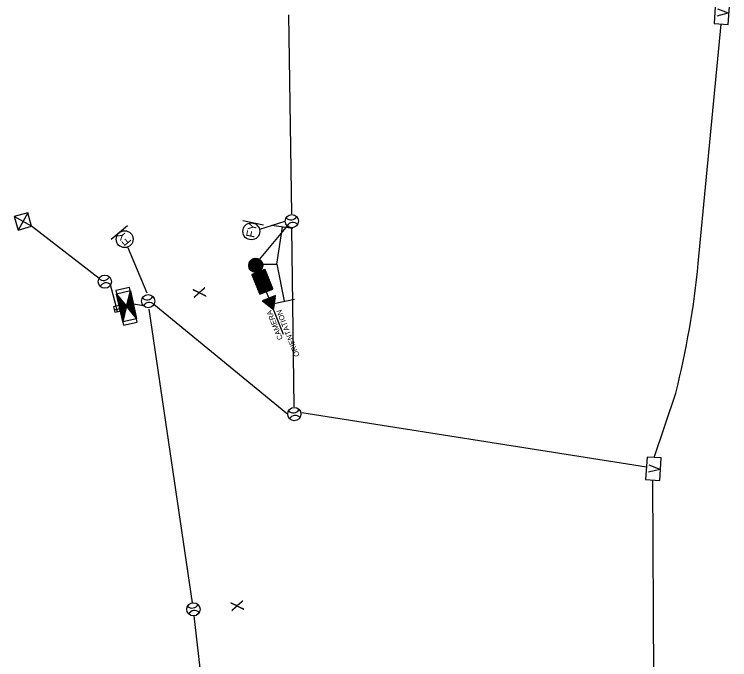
# Model space of a CAD drawing. Extents: x 601562 to 605316, y 332050 to 402250.
# Drawn here: x 601780.7 to 602185.9, y 355227.3 to 355592.7 of the extents above; entities that cross this region are included whole.
import ezdxf

# ---------------------------------------------------------------- set-up
doc = ezdxf.new("R2010")
doc.units = 0
for name, color, linetype in [('Default', 7, 'Continuous'), ('P_FTMS', 7, 'Continuous'), ('P_FTMSConduit', 7, 'Continuous'), ('P_MISC_TXT_1A', 7, 'Continuous')]:
    doc.layers.add(name, color=color, linetype=linetype)

# ---------------------------------------------------------------- blocks, each defined once
blk = doc.blocks.new('FMB_1')
at = {"layer": 'P_FTMS'}
for p, q in [((24.4, -24.4), (-24.4, 24.4)), ((-24.4, -24.4), (24.4, 24.4))]:
    blk.add_line(p, q, dxfattribs=at)
blk.add_lwpolyline([(24.4, -24.4), (24.4, 24.4), (-24.4, 24.4), (-24.4, -24.4)], close=True, dxfattribs=at)
blk = doc.blocks.new('POINT_DISPLAY')
at = {"layer": 'Default'}
blk.add_line((0, 0), (0, 0), dxfattribs=at)
blk = doc.blocks.new('FCS')
at = {"layer": 'P_FTMS'}
for p, q in [((-92.7, 0), (0, 0)), ((1.3, -0.8), (4.9, 2.8)), ((4.9, -2.8), (1.3, 0.8)), ((2.6, -1.5), (9.8, 5.7)), ((9.8, -5.7), (2.6, 1.5)), ((3.9, -2.3), (14.7, 8.5)), ((14.7, -8.5), (3.9, 2.3)), ((5.2, -3), (19.6, 11.3)), ((19.6, -11.3), (5.2, 3)), ((6.6, -3.8), (24.5, 14.1)), ((24.5, -14.2), (6.6, 3.8)), ((7.9, -4.5), (29.4, 17)), ((29.4, -17), (7.9, 4.5)), ((9.2, -5.3), (34.3, 19.8)), ((34.3, -19.8), (9.2, 5.3)), ((10.5, -6.1), (39.2, 22.6)), ((39.2, -22.6), (10.5, 6.1)), ((11.8, -6.8), (42, 23.4)), ((42, -23.4), (11.8, 6.8)), ((13.1, -7.6), (42, 21.3)), ((42, -21.3), (13.1, 7.6)), ((14.4, -8.3), (42, 19.3)), ((42, -19.3), (14.4, 8.3)), ((15.7, -9.1), (42, 17.2)), ((42, -17.2), (15.7, 9.1)), ((17, -9.8), (42, 15.1)), ((42, -15.1), (17.1, 9.8)), ((18.4, -10.6), (42, 13.1)), ((42, -13.1), (18.4, 10.6)), ((42, -11), (19.7, 11.4)), ((19.7, -11.4), (42, 11)), ((42, -8.9), (21, 12.1)), ((21, -12.1), (42, 8.9)), ((42, -6.8), (22.3, 12.9)), ((22.3, -12.9), (42, 6.8)), ((42, -4.8), (23.6, 13.6)), ((23.6, -13.6), (42, 4.8)), ((42, -2.7), (24.9, 14.4)), ((24.9, -14.4), (42, 2.7)), ((42, -0.6), (26.2, 15.1)), ((26.2, -15.2), (42, 0.6)), ((42, 1.4), (27.5, 15.9)), ((42, 3.5), (28.9, 16.7)), ((42, 5.6), (30.2, 17.4)), ((42, 7.6), (31.5, 18.2)), ((42, 9.7), (32.8, 18.9)), ((42, 11.8), (34.1, 19.7)), ((42, 13.8), (35.4, 20.4)), ((42, 15.9), (36.7, 21.2)), ((42, 18), (38, 22)), ((42, 20.1), (39.3, 22.7)), ((42, 22.1), (40.7, 23.5)), ((42, 24.2), (42, 24.2)), ((66.4, 0.1), (42, 0.1)), ((66.4, -24.3), (115.2, 24.5)), ((66.4, -13.9), (104.8, 24.5)), ((66.4, -3.6), (94.5, 24.5)), ((66.4, 6.8), (84.1, 24.5)), ((66.4, 17.1), (73.8, 24.5)), ((66.4, -22.2), (113.1, 24.5)), ((66.4, -11.9), (102.8, 24.5)), ((66.4, -1.5), (92.4, 24.5)), ((66.4, 8.8), (82.1, 24.5)), ((66.4, 19.2), (71.7, 24.5)), ((66.4, -20.1), (111, 24.5)), ((66.4, -9.8), (100.7, 24.5)), ((66.4, 0.6), (90.3, 24.5)), ((66.4, 10.9), (80, 24.5)), ((66.4, 21.2), (69.6, 24.5)), ((66.4, -18.1), (109, 24.5)), ((66.4, -7.7), (98.6, 24.5)), ((66.4, 2.6), (88.3, 24.5)), ((66.4, 13), (77.9, 24.5)), ((66.4, 23.3), (67.6, 24.5)), ((66.4, -16), (106.9, 24.5)), ((66.4, -5.7), (96.5, 24.5)), ((66.4, 4.7), (86.2, 24.5)), ((66.4, 15), (75.9, 24.5)), ((114, -24.3), (66.4, 23.3)), ((111.9, -24.3), (66.4, 21.2)), ((109.9, -24.3), (66.4, 19.2)), ((107.8, -24.3), (66.4, 17.1)), ((105.7, -24.3), (66.4, 15)), ((103.6, -24.3), (66.4, 13)), ((101.6, -24.3), (66.4, 10.9)), ((99.5, -24.3), (66.4, 8.8)), ((97.4, -24.3), (66.4, 6.8)), ((95.4, -24.3), (66.4, 4.7)), ((93.3, -24.3), (66.4, 2.6)), ((91.2, -24.3), (66.4, 0.6)), ((116.1, -24.3), (67.3, 24.5)), ((68.5, -24.3), (117.2, 24.5)), ((118.1, -24.3), (69.4, 24.5)), ((70.5, -24.3), (119.3, 24.5)), ((120.2, -24.3), (71.4, 24.5)), ((72.6, -24.3), (121.4, 24.5)), ((122.3, -24.3), (73.5, 24.5)), ((74.7, -24.3), (123.4, 24.5)), ((124.3, -24.3), (75.6, 24.5)), ((76.7, -24.3), (125.5, 24.5)), ((126.4, -24.3), (77.6, 24.5)), ((78.8, -24.3), (127.6, 24.5)), ((128.5, -24.3), (79.7, 24.5)), ((80.9, -24.3), (129.7, 24.5)), ((130.5, -24.3), (81.8, 24.5)), ((83, -24.3), (131.7, 24.5)), ((132.6, -24.3), (83.8, 24.5)), ((85, -24.3), (133.8, 24.5)), ((134.7, -24.3), (85.9, 24.5)), ((87.1, -24.3), (135.9, 24.5)), ((136.7, -24.3), (88, 24.5)), ((89.2, -24.3), (137.9, 24.5)), ((138.8, -24.3), (90.1, 24.5)), ((91.2, -24.3), (139.6, 24.1)), ((139.6, -22.9), (92.1, 24.5)), ((93.3, -24.3), (139.6, 22)), ((139.6, -20.9), (94.2, 24.5)), ((95.4, -24.3), (139.6, 19.9)), ((139.6, -18.8), (96.3, 24.5)), ((97.4, -24.3), (139.6, 17.8)), ((139.6, -16.7), (98.3, 24.5)), ((99.5, -24.3), (139.6, 15.8)), ((139.6, -14.7), (100.4, 24.5)), ((101.6, -24.3), (139.6, 13.7)), ((139.6, -12.6), (102.5, 24.5)), ((103.6, -24.3), (139.6, 11.6)), ((139.6, -10.5), (104.5, 24.5)), ((105.7, -24.3), (139.6, 9.6)), ((139.6, -8.5), (106.6, 24.5)), ((107.8, -24.3), (139.6, 7.5)), ((139.6, -6.4), (108.7, 24.5)), ((109.9, -24.3), (139.6, 5.4)), ((110.4, 0.1), (112, 0.1)), ((139.6, -4.3), (110.7, 24.5)), ((111.9, -24.3), (139.6, 3.4)), ((139.6, -2.3), (112.8, 24.5)), ((114, -24.3), (139.6, 1.3)), ((139.6, -0.2), (114.9, 24.5)), ((139.6, 1.9), (116.9, 24.5)), ((139.6, 4), (119, 24.5)), ((139.6, 6), (121.1, 24.5)), ((139.6, 8.1), (123.2, 24.5)), ((139.6, 10.2), (125.2, 24.5)), ((139.6, 12.2), (127.3, 24.5)), ((139.6, 14.3), (129.4, 24.5)), ((139.6, 16.4), (131.4, 24.5)), ((139.6, 18.4), (133.5, 24.5)), ((139.6, 20.5), (135.6, 24.5)), ((139.6, 22.6), (137.6, 24.5)), ((139.6, 0.6), (163.5, 24.4)), ((165.5, -24.2), (139.6, 1.6)), ((139.7, -1.4), (165.4, 24.4)), ((139.8, 2.9), (161.2, 24.3)), ((139.8, -3.3), (167.3, 24.2)), ((167.3, -24), (139.9, 3.5)), ((140.1, 5.2), (158.7, 23.9)), ((169.1, -23.7), (140.1, 5.3)), ((140.2, -5), (169.1, 23.9)), ((140.6, -6.7), (170.7, 23.4)), ((170.8, -23.3), (140.6, 6.9)), ((141, 8.2), (155.9, 23.1)), ((141.1, -8.2), (172.3, 23)), ((172.3, -22.7), (141.1, 8.5)), ((141.7, -9.7), (173.8, 22.3)), ((173.8, -22.2), (141.7, 9.9)), ((142.3, -11.1), (175.2, 21.7)), ((175.2, -21.5), (142.4, 11.3)), ((142.7, 12), (152.2, 21.5)), ((143.1, -12.4), (176.5, 20.9)), ((176.5, -20.7), (143.1, 12.7)), ((143.9, -13.7), (177.7, 20.1)), ((177.8, -19.9), (143.9, 13.9)), ((144.8, -14.9), (179, 19.3)), ((178.9, -19), (144.8, 15.1)), ((180.1, -18.1), (145.7, 16.3)), ((145.8, -16), (180.1, 18.3)), ((146.7, -17.1), (181.1, 17.3)), ((181.2, -17.1), (146.8, 17.3)), ((182.1, -16), (147.8, 18.3)), ((147.8, -18.1), (182.2, 16.3)), ((183.1, -14.9), (148.9, 19.3)), ((149, -19), (183.1, 15.1)), ((184, -13.7), (150.1, 20.1)), ((150.1, -19.9), (184, 13.9)), ((184.8, -12.4), (151.4, 20.9)), ((151.4, -20.7), (184.8, 12.7)), ((185.5, -11.2), (152.7, 21.7)), ((152.7, -21.5), (185.5, 11.3)), ((186.2, -9.7), (154.1, 22.3)), ((154.1, -22.2), (186.2, 9.9)), ((186.8, -8.2), (155.6, 23)), ((155.6, -22.7), (186.8, 8.5)), ((157.1, -23.3), (187.3, 6.9)), ((187.3, -6.7), (157.2, 23.4)), ((187.7, -5), (158.8, 23.9)), ((158.8, -23.7), (187.8, 5.3)), ((188.1, -3.3), (160.5, 24.2)), ((160.6, -24), (188, 3.5)), ((188.2, -1.4), (162.4, 24.4)), ((162.4, -24.2), (188.2, 1.6)), ((188.3, 0.6), (164.4, 24.5)), ((188.1, 2.9), (166.7, 24.3)), ((187.8, 5.2), (169.2, 23.9)), ((186.9, 8.2), (172, 23.1)), ((185.2, 12), (175.7, 21.4)), ((27.5, -15.9), (42, -1.4)), ((28.9, -16.7), (42, -3.5)), ((30.2, -17.4), (42, -5.6)), ((31.5, -18.2), (42, -7.6)), ((32.8, -18.9), (42, -9.7)), ((34.1, -19.7), (42, -11.8)), ((35.4, -20.5), (42, -13.8)), ((36.7, -21.2), (42, -15.9)), ((38, -22), (42, -18)), ((39.3, -22.7), (42, -20.1)), ((40.7, -23.5), (42, -22.1)), ((42, -24.2), (42, -24.2)), ((89.2, -24.3), (66.4, -1.5)), ((87.1, -24.3), (66.4, -3.6)), ((85, -24.3), (66.4, -5.7)), ((83, -24.3), (66.4, -7.7)), ((80.9, -24.3), (66.4, -9.8)), ((78.8, -24.3), (66.4, -11.9)), ((76.7, -24.3), (66.4, -13.9)), ((74.7, -24.3), (66.4, -16)), ((72.6, -24.3), (66.4, -18.1)), ((70.5, -24.3), (66.4, -20.1)), ((68.5, -24.3), (66.4, -22.2)), ((116.1, -24.3), (139.6, -0.8)), ((118.1, -24.3), (139.6, -2.8)), ((120.2, -24.3), (139.6, -4.9)), ((122.3, -24.3), (139.6, -7)), ((124.3, -24.3), (139.6, -9.1)), ((126.4, -24.3), (139.6, -11.1)), ((128.5, -24.3), (139.6, -13.2)), ((130.5, -24.3), (139.6, -15.3)), ((132.6, -24.3), (139.6, -17.3)), ((134.7, -24.3), (139.6, -19.4)), ((136.7, -24.3), (139.6, -21.5)), ((138.8, -24.3), (139.6, -23.5)), ((163.4, -24.2), (139.6, -0.4)), ((161.2, -24.1), (139.7, -2.6)), ((158.7, -23.6), (140.2, -5.1)), ((155.8, -22.8), (141, -8)), ((152, -21), (142.7, -11.8)), ((164.5, -24.2), (188.2, -0.4)), ((166.7, -24.1), (188.1, -2.6)), ((169.2, -23.7), (187.7, -5.1)), ((172.1, -22.8), (186.9, -8)), ((175.9, -21), (185.2, -11.8))]:
    blk.add_line(p, q, dxfattribs=at)
for points in [[(42, -24.3), (42, 24.3), (0, 0)], [(139.6, 24.5), (66.4, 24.5), (66.4, -24.3), (139.6, -24.3)]]:
    blk.add_lwpolyline(points, close=True, dxfattribs=at)
blk.add_circle((163.9, 0.1), 24.4, dxfattribs=at)
for p in [(0, 0), (110.4, 0.1)]:
    blk.add_blockref('POINT_DISPLAY', p, dxfattribs=at)
at = {"layer": 'P_MISC_TXT_1A'}
for s, height, p in [('CAMERA', 18.29, (-105.8, 7)), ('ORIENTATION', 18.288, (-181.1, -25))]:
    blk.add_text(s, height=height, rotation=360, dxfattribs=at).set_placement(p)
blk = doc.blocks.new('FTMS_FCV')
at = {"layer": 'P_FTMS'}
blk.add_line((12.7, 16.3), (0.6, -21.9), dxfattribs=at)
blk.add_lwpolyline([(39.1, 24.4), (-39.1, 24.4), (-39.1, -24.4), (39.1, -24.4)], close=True, dxfattribs=at)
blk.add_lwpolyline([(-12.1, 16.2), (0.6, -21.9)], dxfattribs=at)
blk = doc.blocks.new('FTMS_FCB')
at = {"layer": 'P_FTMS'}
for p, q in [((-48.3, 24.1), (-48, 24.4)), ((-45.5, 22.7), (-47.1, 24.4)), ((-46.9, 23.4), (-46, 24.4)), ((-45.5, 22.8), (-43.9, 24.4)), ((-41.4, 20.7), (-45.1, 24.4)), ((-44.1, 22.1), (-41.8, 24.4)), ((-37.2, 18.6), (-43, 24.4)), ((-42.8, 21.4), (-39.8, 24.4)), ((-41.4, 20.7), (-37.7, 24.4)), ((-33.1, 16.5), (-40.9, 24.4)), ((-40, 20), (-35.6, 24.4)), ((-29, 14.5), (-38.9, 24.4)), ((-38.6, 19.3), (-33.6, 24.4)), ((-37.2, 18.6), (-31.5, 24.4)), ((-24.8, 12.4), (-36.8, 24.4)), ((-35.9, 17.9), (-29.4, 24.4)), ((-20.7, 10.3), (-34.7, 24.4)), ((-34.5, 17.2), (-27.3, 24.4)), ((-33.1, 16.5), (-25.3, 24.4)), ((-16.5, 8.3), (-32.7, 24.4)), ((-31.7, 15.9), (-23.2, 24.4)), ((-12.4, 6.2), (-30.6, 24.4)), ((-30.3, 15.2), (-21.1, 24.4)), ((-29, 14.5), (-19.1, 24.4)), ((-8.3, 4.1), (-28.5, 24.4)), ((-27.6, 13.8), (-17, 24.4)), ((-4.1, 2.1), (-26.4, 24.4)), ((-26.2, 13.1), (-14.9, 24.4)), ((-24.8, 12.4), (-12.9, 24.4)), ((0, 0), (-24.4, 24.4)), ((-24.4, -24.4), (0, 0)), ((-23.5, 11.7), (-10.8, 24.4)), ((1.4, 0.7), (-22.3, 24.4)), ((-22.1, 11), (-8.7, 24.4)), ((-20.7, 10.3), (-6.7, 24.4)), ((2.8, 1.4), (-20.2, 24.4)), ((-19.3, 9.7), (-4.6, 24.4)), ((4.1, 2.1), (-18.2, 24.4)), ((-17.9, 9), (-2.5, 24.4)), ((-16.6, 8.3), (-0.4, 24.4)), ((5.5, 2.8), (-16.1, 24.4)), ((-15.2, 7.6), (1.6, 24.4)), ((6.9, 3.4), (-14, 24.4)), ((-13.8, 6.9), (3.7, 24.4)), ((-12.4, 6.2), (5.8, 24.4)), ((8.3, 4.1), (-12, 24.4)), ((-11, 5.5), (7.8, 24.4)), ((9.7, 4.8), (-9.9, 24.4)), ((-9.7, 4.8), (9.9, 24.4)), ((-8.3, 4.1), (12, 24.4)), ((11, 5.5), (-7.8, 24.4)), ((-6.9, 3.4), (14, 24.4)), ((12.4, 6.2), (-5.8, 24.4)), ((-5.5, 2.8), (16.1, 24.4)), ((-4.1, 2.1), (18.2, 24.4)), ((13.8, 6.9), (-3.7, 24.4)), ((-2.8, 1.4), (20.2, 24.4)), ((15.2, 7.6), (-1.6, 24.4)), ((-1.4, 0.7), (22.3, 24.4)), ((0, 0), (24.4, 24.4)), ((24.4, -24.4), (0, 0)), ((16.6, 8.3), (0.4, 24.4)), ((17.9, 9), (2.5, 24.4)), ((4.1, 2.1), (26.5, 24.4)), ((19.3, 9.7), (4.6, 24.4)), ((20.7, 10.3), (6.7, 24.4)), ((8.3, 4.1), (28.5, 24.4)), ((22.1, 11), (8.7, 24.4)), ((23.4, 11.7), (10.8, 24.4)), ((12.4, 6.2), (30.6, 24.4)), ((24.8, 12.4), (12.9, 24.4)), ((26.2, 13.1), (14.9, 24.4)), ((16.6, 8.3), (32.7, 24.4)), ((27.6, 13.8), (17, 24.4)), ((29, 14.5), (19.1, 24.4)), ((20.7, 10.3), (34.7, 24.4)), ((30.3, 15.2), (21.1, 24.4)), ((31.7, 15.9), (23.2, 24.4)), ((24.8, 12.4), (36.8, 24.4)), ((33.1, 16.6), (25.3, 24.4)), ((34.5, 17.2), (27.3, 24.4)), ((29, 14.5), (38.9, 24.4)), ((35.9, 17.9), (29.4, 24.4)), ((37.2, 18.6), (31.5, 24.4)), ((33.1, 16.6), (40.9, 24.4)), ((38.6, 19.3), (33.5, 24.4)), ((40, 20), (35.6, 24.4)), ((37.2, 18.6), (43, 24.4)), ((41.4, 20.7), (37.7, 24.4)), ((42.8, 21.4), (39.8, 24.4)), ((41.4, 20.7), (45.1, 24.4)), ((44.1, 22.1), (41.8, 24.4)), ((45.5, 22.8), (43.9, 24.4)), ((45.5, 22.8), (47.1, 24.4)), ((46.9, 23.5), (46, 24.4)), ((48.3, 24.1), (48, 24.4)), ((-48, -24.4), (-48.3, -24.1)), ((-47.2, -24.4), (-45.5, -22.8)), ((-45.9, -24.4), (-46.9, -23.5)), ((-43.9, -24.4), (-45.5, -22.8)), ((-45.1, -24.4), (-41.4, -20.7)), ((-41.8, -24.4), (-44.1, -22.1)), ((-43, -24.4), (-37.3, -18.6)), ((-39.7, -24.4), (-42.8, -21.4)), ((-37.7, -24.4), (-41.4, -20.7)), ((-41, -24.4), (-33.1, -16.6)), ((-35.6, -24.4), (-40, -20)), ((-38.9, -24.4), (-29, -14.5)), ((-33.5, -24.4), (-38.6, -19.3)), ((-31.5, -24.4), (-37.2, -18.6)), ((-36.8, -24.4), (-24.8, -12.4)), ((-29.4, -24.4), (-35.9, -17.9)), ((-34.8, -24.4), (-20.7, -10.4)), ((-27.3, -24.4), (-34.5, -17.2)), ((-25.3, -24.4), (-33.1, -16.6)), ((-32.7, -24.4), (-16.6, -8.3)), ((-23.2, -24.4), (-31.7, -15.9)), ((-30.6, -24.4), (-12.4, -6.2)), ((-21.1, -24.4), (-30.3, -15.2)), ((-19, -24.4), (-29, -14.5)), ((-28.5, -24.4), (-8.3, -4.1)), ((-17, -24.4), (-27.6, -13.8)), ((-26.5, -24.4), (-4.1, -2.1)), ((-14.9, -24.4), (-26.2, -13.1)), ((-12.8, -24.4), (-24.8, -12.4)), ((-10.8, -24.4), (-23.4, -11.7)), ((-22.3, -24.4), (1.4, -0.7)), ((-8.7, -24.4), (-22.1, -11)), ((-6.6, -24.4), (-20.7, -10.3)), ((-20.3, -24.4), (2.8, -1.4)), ((-4.6, -24.4), (-19.3, -9.7)), ((-18.2, -24.4), (4.1, -2.1)), ((-2.5, -24.4), (-17.9, -9)), ((-0.4, -24.4), (-16.6, -8.3)), ((-16.1, -24.4), (5.5, -2.8)), ((1.6, -24.4), (-15.2, -7.6)), ((-14.1, -24.4), (6.9, -3.4)), ((3.7, -24.4), (-13.8, -6.9)), ((5.8, -24.4), (-12.4, -6.2)), ((-12, -24.4), (8.3, -4.1)), ((7.8, -24.4), (-11, -5.5)), ((-9.9, -24.4), (9.7, -4.8)), ((9.9, -24.4), (-9.7, -4.8)), ((12, -24.4), (-8.3, -4.1)), ((-7.8, -24.4), (11, -5.5)), ((14.1, -24.4), (-6.9, -3.5)), ((-5.8, -24.4), (12.4, -6.2)), ((16.1, -24.4), (-5.5, -2.8)), ((18.2, -24.4), (-4.1, -2.1)), ((-3.7, -24.4), (13.8, -6.9)), ((20.3, -24.4), (-2.8, -1.4)), ((-1.6, -24.4), (15.2, -7.6)), ((22.3, -24.4), (-1.4, -0.7)), ((0.4, -24.4), (16.6, -8.3)), ((2.5, -24.4), (17.9, -9)), ((26.5, -24.4), (4.1, -2.1)), ((4.6, -24.4), (19.3, -9.7)), ((6.6, -24.4), (20.7, -10.3)), ((28.5, -24.4), (8.3, -4.1)), ((8.7, -24.4), (22.1, -11)), ((10.8, -24.4), (23.4, -11.7)), ((30.6, -24.4), (12.4, -6.2)), ((12.8, -24.4), (24.8, -12.4)), ((14.9, -24.4), (26.2, -13.1)), ((32.7, -24.4), (16.6, -8.3)), ((17, -24.4), (27.6, -13.8)), ((19.1, -24.4), (29, -14.5)), ((34.7, -24.4), (20.7, -10.3)), ((21.1, -24.4), (30.3, -15.2)), ((23.2, -24.4), (31.7, -15.9)), ((36.8, -24.4), (24.8, -12.4)), ((25.3, -24.4), (33.1, -16.6)), ((27.3, -24.4), (34.5, -17.2)), ((38.9, -24.4), (29, -14.5)), ((29.4, -24.4), (35.9, -17.9)), ((31.5, -24.4), (37.2, -18.6)), ((40.9, -24.4), (33.1, -16.6)), ((33.5, -24.4), (38.6, -19.3)), ((35.6, -24.4), (40, -20)), ((43, -24.4), (37.2, -18.6)), ((37.7, -24.4), (41.4, -20.7)), ((39.7, -24.4), (42.8, -21.4)), ((45.1, -24.4), (41.4, -20.7)), ((41.8, -24.4), (44.1, -22.1)), ((43.9, -24.4), (45.5, -22.8)), ((47.2, -24.4), (45.5, -22.8)), ((46, -24.4), (46.9, -23.5)), ((48, -24.4), (48.3, -24.1))]:
    blk.add_line(p, q, dxfattribs=at)
for points in [[(61, 24.4), (-61, 24.4), (-61, -24.4), (61, -24.4)], [(48.8, 24.4), (-48.8, 24.4), (-48.8, -24.4), (48.8, -24.4)], [(48.8, 24.4), (0, 0), (-48.8, 24.4)], [(48.8, -24.4), (-48.8, -24.4), (0, 0)]]:
    blk.add_lwpolyline(points, close=True, dxfattribs=at)
blk = doc.blocks.new('FTMS')
at = {"layer": 'P_FTMS'}
for p, q in [((-23.3, 0), (25.5, 0)), ((0, 24.3), (0, -24.5))]:
    blk.add_line(p, q, dxfattribs=at)
blk.add_lwpolyline([(25.5, -24.5), (25.5, 24.3), (-23.3, 24.3), (-23.3, -24.5)], close=True, dxfattribs=at)
blk = doc.blocks.new('FTMS_FERA')
at = {"layer": 'P_FTMS'}
for p, q in [((-65.1, 36.6), (-65.1, -36.6)), ((65.1, 0), (-65.1, 0))]:
    blk.add_line(p, q, dxfattribs=at)
blk = doc.blocks.new('FTMS_FFY')
at = {"layer": 'P_FTMS'}
blk.add_line((36.6, -45.7), (36.6, 45.7), dxfattribs=at)
blk.add_circle((0, 0), 36.6, dxfattribs=at)
blk.add_text('FY', height=36.58, dxfattribs=at).set_placement((-26.8, -18.3))

msp = doc.modelspace()

# ---------------------------------------------------------------- linework, layer by layer
at = {"layer": 'P_FTMS'}
msp.add_line((601921.41, 355451.2), (601929.36, 355451.2), dxfattribs=at)
for centre in [(601937.94, 355475.61), (601831.99, 355441.36), (601856.54, 355430.31), (601939.33, 355366.39), (601882.18, 355255.85)]:
    msp.add_circle(centre, 3.75, dxfattribs=at)
for centre, start, end in [((601937.34, 355480.07), 224.5444, 330.8), ((601938.54, 355471.15), 44.5444, 150.8), ((601831.39, 355445.82), 224.5444, 330.8), ((601832.59, 355436.9), 44.5444, 150.8), ((601855.94, 355434.77), 224.5444, 330.8), ((601857.14, 355425.85), 44.5444, 150.8), ((601938.73, 355370.85), 224.5444, 330.8), ((601939.93, 355361.93), 44.5444, 150.8), ((601881.58, 355260.31), 224.5444, 330.8), ((601882.78, 355251.39), 44.5444, 150.8)]:
    msp.add_arc(centre, 3.75, start, end, dxfattribs=at)
at = {"layer": 'P_FTMSConduit'}
for p, q in [((601936.12, 355592.53), (601937.64, 355479.81)), ((601935.37, 355473.15), (601919.48, 355453.98)), ((601933.96, 355475.39), (601919.54, 355470.99)), ((601828.71, 355443.19), (601790.54, 355472.7)), ((601937.75, 355471.82), (601939.12, 355370.58)), ((601855.94, 355434.77), (601845.06, 355460.98)), ((601838.47, 355427.48), (601835.26, 355439.53)), ((601853.87, 355427.68), (601848.14, 355428.68)), ((601935.58, 355366.16), (601859.81, 355428.48)), ((602138.79, 355336.24), (601943.53, 355367.05)), ((602142.95, 355209.66), (602142.34, 355329.01)), ((601902.2, 355079.35), (601882.6, 355252.12))]:
    msp.add_line(p, q, dxfattribs=at)
for points in [[(602168.16, 355451.72), (602181.13, 355587.23)], [(601881.59, 355259.55), (601857.14, 355425.85)], [(602143.15, 355341.81), (602155.38, 355378.2)]]:
    msp.add_lwpolyline(points, dxfattribs=at)
msp.add_arc((601670.53, 355500.38), 500, 345.8565, 354.4153, dxfattribs=at)

# ---------------------------------------------------------------- block references
at = {"layer": 'P_FTMS'}
for name, p, xscale, yscale, rotation in [('FTMS_FCV', (602181.53, 355593.63), 0.1640416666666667, 0.16404166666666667, 86.34463929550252), ('FMB_1', (601785.63, 355475.51), 0.16404166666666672, 0.1640416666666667, 105.22140980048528), ('FTMS_FFY', (601843.22, 355465.42), 0.1312333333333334, 0.13123333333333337, 129.86466640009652), ('FTMS_FFY', (601914.97, 355469.86), 0.1312333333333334, 0.1312333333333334, 77.68700292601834), ('FTMS_FERA', (601930.98, 355461.76), 0.16404166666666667, 0.1640416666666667, -98.71987256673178), ('FCS', (601927.51, 355425.58), 0.1640416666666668, 0.16404166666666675, 111.86873675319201), ('FTMS_FERA', (601931.5, 355440.73), 0.16404166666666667, 0.1640416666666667, 101.55328706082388), ('FTMS_FCB', (601844.32, 355427.41), 0.16404166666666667, 0.1640416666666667, 102.51989930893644), ('FTMS', (601838.83, 355425.85), 0.06561666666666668, 0.06561666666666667, 102.51989930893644), ('FTMS_FCV', (602142.74, 355335.41), 0.1640416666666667, 0.16404166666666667, 86.34463929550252)]:
    msp.add_blockref(name, p, dxfattribs=dict(at, xscale=xscale, yscale=yscale, rotation=rotation))

# ---------------------------------------------------------------- texts
at = {"layer": 'P_FTMSConduit'}
for p in [(601889.5, 355432.47), (601910.93, 355255.15)]:
    msp.add_text('X', height=7, rotation=97.7394, dxfattribs=at).set_placement(p)

doc.saveas('drawing.dxf')
